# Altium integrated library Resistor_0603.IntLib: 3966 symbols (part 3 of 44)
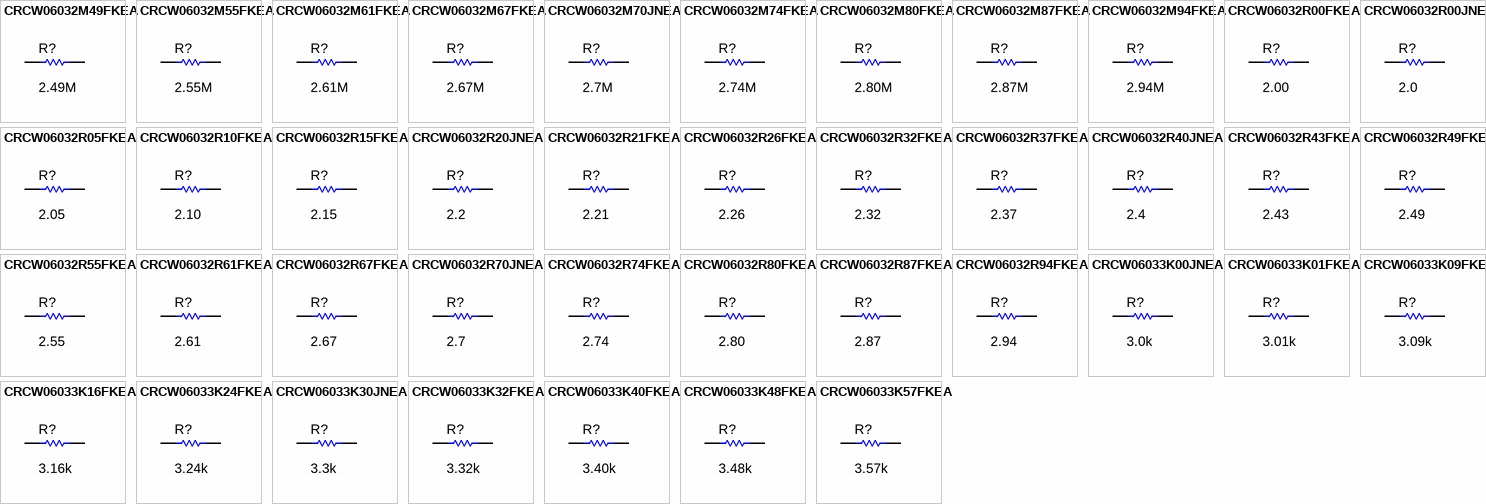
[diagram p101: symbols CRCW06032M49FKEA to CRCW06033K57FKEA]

## CRCW06032R37FKEA
designator R?  ValueDisplayed: 2.37  (hidden comment: CRCW06032R37FKEA)
RES, 2.37, 1%, 0.1 W, 0603; Manufacturer: Vishay-Dale; CompType: Resistor; Value: 2.37; Value_Code: 2R37; Tolerance_%: 1; Power_W: 0.1; Value2: 0.1W; VDC_V: 75; TempCo: 100 ppm/C; SizeArea_mm2: 1.28; SizeX_mm: 1.6; SizeY_mm: 0.8; EIA_Code: E96; U/M: EA; AEC Category: Q200
signal-integrity model Resistor
simulation model Resistor
footprint 0603
footprint 0603M
footprint 0603L
footprint 0603_HV
footprint 0603S
pins: 1, 2

## CRCW06032R40JNEA
designator R?  ValueDisplayed: 2.4  (hidden comment: CRCW06032R40JNEA)
RES, 2.4, 5%, 0.1 W, 0603; Manufacturer: Vishay-Dale; CompType: Resistor; Value: 2.4; Value_Code: 2R40; Tolerance_%: 5; Power_W: 0.1; Value2: 0.1W; VDC_V: 75; TempCo: 200 ppm/C; SizeArea_mm2: 1.28; SizeX_mm: 1.6; SizeY_mm: 0.8; SizeZ_mm: 1; EIA_Code: E24; U/M: EA; AEC Category: Q200
signal-integrity model Resistor
simulation model Resistor
footprint 0603
footprint 0603M
footprint 0603L
footprint 0603_HV
footprint 0603S
pins: 1, 2

## CRCW06032R43FKEA
designator R?  ValueDisplayed: 2.43  (hidden comment: CRCW06032R43FKEA)
RES, 2.43, 1%, 0.1 W, 0603; Manufacturer: Vishay-Dale; CompType: Resistor; Value: 2.43; Value_Code: 2R43; Tolerance_%: 1; Power_W: 0.1; Value2: 0.1W; VDC_V: 75; TempCo: 100 ppm/C; SizeArea_mm2: 1.28; SizeX_mm: 1.6; SizeY_mm: 0.8; EIA_Code: E96; U/M: EA; AEC Category: Q200
signal-integrity model Resistor
simulation model Resistor
footprint 0603
footprint 0603M
footprint 0603L
footprint 0603_HV
footprint 0603S
pins: 1, 2

## CRCW06032R49FKEA
designator R?  ValueDisplayed: 2.49  (hidden comment: CRCW06032R49FKEA)
RES, 2.49, 1%, 0.1 W, 0603; Manufacturer: Vishay-Dale; CompType: Resistor; Value: 2.49; Value_Code: 2R49; Tolerance_%: 1; Power_W: 0.1; Value2: 0.1W; VDC_V: 75; TempCo: 100 ppm/C; SizeArea_mm2: 1.28; SizeX_mm: 1.6; SizeY_mm: 0.8; EIA_Code: E96; U/M: EA; AEC Category: Q200
signal-integrity model Resistor
simulation model Resistor
footprint 0603
footprint 0603M
footprint 0603L
footprint 0603_HV
footprint 0603S
pins: 1, 2

## CRCW06032R55FKEA
designator R?  ValueDisplayed: 2.55  (hidden comment: CRCW06032R55FKEA)
RES, 2.55, 1%, 0.1 W, 0603; Manufacturer: Vishay-Dale; CompType: Resistor; Value: 2.55; Value_Code: 2R55; Tolerance_%: 1; Power_W: 0.1; Value2: 0.1W; VDC_V: 75; TempCo: 100 ppm/C; SizeArea_mm2: 1.28; SizeX_mm: 1.6; SizeY_mm: 0.8; EIA_Code: E96; U/M: EA; AEC Category: Q200
signal-integrity model Resistor
simulation model Resistor
footprint 0603
footprint 0603M
footprint 0603L
footprint 0603_HV
footprint 0603S
pins: 1, 2

## CRCW06032R61FKEA
designator R?  ValueDisplayed: 2.61  (hidden comment: CRCW06032R61FKEA)
RES, 2.61, 1%, 0.1 W, 0603; Manufacturer: Vishay-Dale; CompType: Resistor; Value: 2.61; Value_Code: 2R61; Tolerance_%: 1; Power_W: 0.1; Value2: 0.1W; VDC_V: 75; TempCo: 100 ppm/C; SizeArea_mm2: 1.28; SizeX_mm: 1.6; SizeY_mm: 0.8; EIA_Code: E96; U/M: EA; AEC Category: Q200
signal-integrity model Resistor
simulation model Resistor
footprint 0603
footprint 0603M
footprint 0603L
footprint 0603_HV
footprint 0603S
pins: 1, 2

## CRCW06032R67FKEA
designator R?  ValueDisplayed: 2.67  (hidden comment: CRCW06032R67FKEA)
RES, 2.67, 1%, 0.1 W, 0603; Manufacturer: Vishay-Dale; CompType: Resistor; Value: 2.67; Value_Code: 2R67; Tolerance_%: 1; Power_W: 0.1; Value2: 0.1W; VDC_V: 75; TempCo: 100 ppm/C; SizeArea_mm2: 1.28; SizeX_mm: 1.6; SizeY_mm: 0.8; EIA_Code: E96; U/M: EA; AEC Category: Q200
signal-integrity model Resistor
simulation model Resistor
footprint 0603
footprint 0603M
footprint 0603L
footprint 0603_HV
footprint 0603S
pins: 1, 2

## CRCW06032R70JNEA
designator R?  ValueDisplayed: 2.7  (hidden comment: CRCW06032R70JNEA)
RES, 2.7, 5%, 0.1 W, 0603; Manufacturer: Vishay-Dale; CompType: Resistor; Value: 2.7; Value_Code: 2R70; Tolerance_%: 5; Power_W: 0.1; Value2: 0.1W; VDC_V: 75; TempCo: 200 ppm/C; SizeArea_mm2: 1.28; SizeX_mm: 1.6; SizeY_mm: 0.8; SizeZ_mm: 1; EIA_Code: E24; U/M: EA; AEC Category: Q200
signal-integrity model Resistor
simulation model Resistor
footprint 0603
footprint 0603M
footprint 0603L
footprint 0603_HV
footprint 0603S
pins: 1, 2

## CRCW06032R74FKEA
designator R?  ValueDisplayed: 2.74  (hidden comment: CRCW06032R74FKEA)
RES, 2.74, 1%, 0.1 W, 0603; Manufacturer: Vishay-Dale; CompType: Resistor; Value: 2.74; Value_Code: 2R74; Tolerance_%: 1; Power_W: 0.1; Value2: 0.1W; VDC_V: 75; TempCo: 100 ppm/C; SizeArea_mm2: 1.28; SizeX_mm: 1.6; SizeY_mm: 0.8; EIA_Code: E96; U/M: EA; AEC Category: Q200
signal-integrity model Resistor
simulation model Resistor
footprint 0603
footprint 0603M
footprint 0603L
footprint 0603_HV
footprint 0603S
pins: 1, 2

## CRCW06032R80FKEA
designator R?  ValueDisplayed: 2.80  (hidden comment: CRCW06032R80FKEA)
RES, 2.80, 1%, 0.1 W, 0603; Manufacturer: Vishay-Dale; CompType: Resistor; Value: 2.80; Res_ohm: 2.8; Value_Code: 2R80; Tolerance_%: 1; Power_W: 0.1; Value2: 0.1W; VDC_V: 75; TempCo: 100 ppm/C; SizeArea_mm2: 1.28; SizeX_mm: 1.6; SizeY_mm: 0.8; EIA_Code: E96; U/M: EA; AEC Category: Q200
signal-integrity model Resistor
simulation model Resistor
footprint 0603
footprint 0603M
footprint 0603L
footprint 0603_HV
footprint 0603S
pins: 1, 2

## CRCW06032R87FKEA
designator R?  ValueDisplayed: 2.87  (hidden comment: CRCW06032R87FKEA)
RES, 2.87, 1%, 0.1 W, 0603; Manufacturer: Vishay-Dale; CompType: Resistor; Value: 2.87; Value_Code: 2R87; Tolerance_%: 1; Power_W: 0.1; Value2: 0.1W; VDC_V: 75; TempCo: 100 ppm/C; SizeArea_mm2: 1.28; SizeX_mm: 1.6; SizeY_mm: 0.8; EIA_Code: E96; U/M: EA; AEC Category: Q200
signal-integrity model Resistor
simulation model Resistor
footprint 0603
footprint 0603M
footprint 0603L
footprint 0603_HV
footprint 0603S
pins: 1, 2

## CRCW06032R94FKEA
designator R?  ValueDisplayed: 2.94  (hidden comment: CRCW06032R94FKEA)
RES, 2.94, 1%, 0.1 W, 0603; Manufacturer: Vishay-Dale; CompType: Resistor; Value: 2.94; Value_Code: 2R94; Tolerance_%: 1; Power_W: 0.1; Value2: 0.1W; VDC_V: 75; TempCo: 100 ppm/C; SizeArea_mm2: 1.28; SizeX_mm: 1.6; SizeY_mm: 0.8; EIA_Code: E96; U/M: EA; AEC Category: Q200
signal-integrity model Resistor
simulation model Resistor
footprint 0603
footprint 0603M
footprint 0603L
footprint 0603_HV
footprint 0603S
pins: 1, 2

## CRCW06033K00JNEA
designator R?  ValueDisplayed: 3.0k  (hidden comment: CRCW06033K00JNEA)
RES, 3.0 k, 5%, 0.1 W, 0603; Manufacturer: Vishay-Dale; CompType: Resistor; Value: 3.0k; Res_ohm: 3000; Value_Code: 3k00; Tolerance_%: 5; Power_W: 0.1; Value2: 0.1W; VDC_V: 75; TempCo: 200 ppm/C; SizeArea_mm2: 1.28; SizeX_mm: 1.6; SizeY_mm: 0.8; SizeZ_mm: 1; EIA_Code: E24; U/M: EA; AEC Category: Q200; Green_Lifecycle: Active; Green_REACh: Passed
signal-integrity model Resistor
simulation model Resistor
footprint 0603
footprint 0603M
footprint 0603L
footprint 0603_HV
footprint 0603S
pins: 1, 2

## CRCW06033K01FKEA
designator R?  ValueDisplayed: 3.01k  (hidden comment: CRCW06033K01FKEA)
RES, 3.01 k, 1%, 0.1 W, 0603; Manufacturer: Vishay-Dale; CompType: Resistor; Value: 3.01k; Res_ohm: 3010; Value_Code: 3k01; Tolerance_%: 1; Power_W: 0.1; Value2: 0.1W; VDC_V: 75; TempCo: 100 ppm/C; SizeArea_mm2: 1.28; SizeX_mm: 1.6; SizeY_mm: 0.8; EIA_Code: E96; U/M: EA; AEC Category: Q200; Green_Lifecycle: Active; Green_REACh: Passed
signal-integrity model Resistor
simulation model Resistor
footprint 0603
footprint 0603M
footprint 0603L
footprint 0603_HV
footprint 0603S
pins: 1, 2

## CRCW06033K09FKEA
designator R?  ValueDisplayed: 3.09k  (hidden comment: CRCW06033K09FKEA)
RES, 3.09 k, 1%, 0.1 W, 0603; Manufacturer: Vishay-Dale; CompType: Resistor; Value: 3.09k; Res_ohm: 3090; Value_Code: 3k09; Tolerance_%: 1; Power_W: 0.1; Value2: 0.1W; VDC_V: 75; TempCo: 100 ppm/C; SizeArea_mm2: 1.28; SizeX_mm: 1.6; SizeY_mm: 0.8; EIA_Code: E96; U/M: EA; AEC Category: Q200; Green_Lifecycle: Active; Green_REACh: Passed
signal-integrity model Resistor
simulation model Resistor
footprint 0603
footprint 0603M
footprint 0603L
footprint 0603_HV
footprint 0603S
pins: 1, 2

## CRCW06033K16FKEA
designator R?  ValueDisplayed: 3.16k  (hidden comment: CRCW06033K16FKEA)
RES, 3.16 k, 1%, 0.1 W, 0603; Manufacturer: Vishay-Dale; CompType: Resistor; Value: 3.16k; Res_ohm: 3160; Value_Code: 3k16; Tolerance_%: 1; Power_W: 0.1; Value2: 0.1W; VDC_V: 75; TempCo: 100 ppm/C; SizeArea_mm2: 1.28; SizeX_mm: 1.6; SizeY_mm: 0.8; EIA_Code: E96; U/M: EA; AEC Category: Q200; Green_Lifecycle: Active; Green_REACh: Passed
signal-integrity model Resistor
simulation model Resistor
footprint 0603
footprint 0603M
footprint 0603L
footprint 0603_HV
footprint 0603S
pins: 1, 2

## CRCW06033K24FKEA
designator R?  ValueDisplayed: 3.24k  (hidden comment: CRCW06033K24FKEA)
RES, 3.24 k, 1%, 0.1 W, 0603; Manufacturer: Vishay-Dale; CompType: Resistor; Value: 3.24k; Res_ohm: 3240; Value_Code: 3k24; Tolerance_%: 1; Power_W: 0.1; Value2: 0.1W; VDC_V: 75; TempCo: 100 ppm/C; SizeArea_mm2: 1.28; SizeX_mm: 1.6; SizeY_mm: 0.8; EIA_Code: E96; U/M: EA; AEC Category: Q200; Green_Lifecycle: Active; Green_REACh: Passed
signal-integrity model Resistor
simulation model Resistor
footprint 0603
footprint 0603M
footprint 0603L
footprint 0603_HV
footprint 0603S
pins: 1, 2

## CRCW06033K30JNEA
designator R?  ValueDisplayed: 3.3k  (hidden comment: CRCW06033K30JNEA)
RES, 3.3 k, 5%, 0.1 W, 0603; Manufacturer: Vishay-Dale; CompType: Resistor; Value: 3.3k; Res_ohm: 3300; Value_Code: 3k30; Tolerance_%: 5; Power_W: 0.1; Value2: 0.1W; VDC_V: 75; TempCo: 200 ppm/C; SizeArea_mm2: 1.28; SizeX_mm: 1.6; SizeY_mm: 0.8; SizeZ_mm: 1; EIA_Code: E24; U/M: EA; AEC Category: Q200; Green_Lifecycle: Active; Green_REACh: Passed
signal-integrity model Resistor
simulation model Resistor
footprint 0603
footprint 0603M
footprint 0603L
footprint 0603_HV
footprint 0603S
pins: 1, 2

## CRCW06033K32FKEA
designator R?  ValueDisplayed: 3.32k  (hidden comment: CRCW06033K32FKEA)
RES, 3.32 k, 1%, 0.1 W, 0603; Manufacturer: Vishay-Dale; CompType: Resistor; Value: 3.32k; Res_ohm: 3320; Value_Code: 3k32; Tolerance_%: 1; Power_W: 0.1; Value2: 0.1W; VDC_V: 75; TempCo: 100 ppm/C; SizeArea_mm2: 1.28; SizeX_mm: 1.6; SizeY_mm: 0.8; EIA_Code: E96; U/M: EA; AEC Category: Q200; Green_Lifecycle: Active; Green_REACh: Passed
signal-integrity model Resistor
simulation model Resistor
footprint 0603
footprint 0603M
footprint 0603L
footprint 0603_HV
footprint 0603S
pins: 1, 2

## CRCW06033K40FKEA
designator R?  ValueDisplayed: 3.40k  (hidden comment: CRCW06033K40FKEA)
RES, 3.40 k, 1%, 0.1 W, 0603; Manufacturer: Vishay-Dale; CompType: Resistor; Value: 3.40k; Res_ohm: 3400; Value_Code: 3k40; Tolerance_%: 1; Power_W: 0.1; Value2: 0.1W; VDC_V: 75; TempCo: 100 ppm/C; SizeArea_mm2: 1.28; SizeX_mm: 1.6; SizeY_mm: 0.8; EIA_Code: E96; U/M: EA; AEC Category: Q200; Green_Lifecycle: Active; Green_REACh: Passed
signal-integrity model Resistor
simulation model Resistor
footprint 0603
footprint 0603M
footprint 0603L
footprint 0603_HV
footprint 0603S
pins: 1, 2

## CRCW06033K48FKEA
designator R?  ValueDisplayed: 3.48k  (hidden comment: CRCW06033K48FKEA)
RES, 3.48 k, 1%, 0.1 W, 0603; Manufacturer: Vishay-Dale; CompType: Resistor; Value: 3.48k; Res_ohm: 3480; Value_Code: 3k48; Tolerance_%: 1; Power_W: 0.1; Value2: 0.1W; VDC_V: 75; TempCo: 100 ppm/C; SizeArea_mm2: 1.28; SizeX_mm: 1.6; SizeY_mm: 0.8; EIA_Code: E96; U/M: EA; AEC Category: Q200; Green_Lifecycle: Active; Green_REACh: Passed
signal-integrity model Resistor
simulation model Resistor
footprint 0603
footprint 0603M
footprint 0603L
footprint 0603_HV
footprint 0603S
pins: 1, 2

## CRCW06033K57FKEA
designator R?  ValueDisplayed: 3.57k  (hidden comment: CRCW06033K57FKEA)
RES, 3.57 k, 1%, 0.1 W, 0603; Manufacturer: Vishay-Dale; CompType: Resistor; Value: 3.57k; Res_ohm: 3570; Value_Code: 3k57; Tolerance_%: 1; Power_W: 0.1; Value2: 0.1W; VDC_V: 75; TempCo: 100 ppm/C; SizeArea_mm2: 1.28; SizeX_mm: 1.6; SizeY_mm: 0.8; EIA_Code: E96; U/M: EA; AEC Category: Q200; Green_Lifecycle: Active; Green_REACh: Passed
signal-integrity model Resistor
simulation model Resistor
footprint 0603
footprint 0603M
footprint 0603L
footprint 0603_HV
footprint 0603S
pins: 1, 2

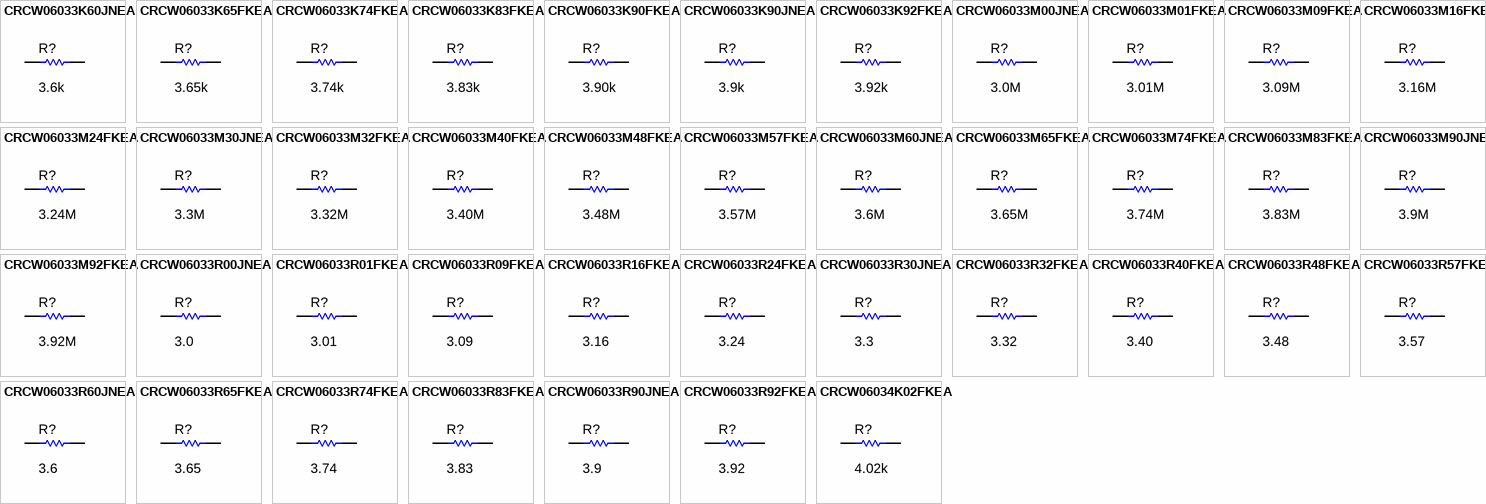
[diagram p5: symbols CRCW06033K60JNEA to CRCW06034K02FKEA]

## CRCW06033K60JNEA
designator R?  ValueDisplayed: 3.6k  (hidden comment: CRCW06033K60JNEA)
RES, 3.6 k, 5%, 0.1 W, 0603; Manufacturer: Vishay-Dale; CompType: Resistor; Value: 3.6k; Res_ohm: 3600; Value_Code: 3k60; Tolerance_%: 5; Power_W: 0.1; Value2: 0.1W; VDC_V: 75; TempCo: 200 ppm/C; SizeArea_mm2: 1.28; SizeX_mm: 1.6; SizeY_mm: 0.8; SizeZ_mm: 1; EIA_Code: E24; U/M: EA; AEC Category: Q200
signal-integrity model Resistor
simulation model Resistor
footprint 0603
footprint 0603M
footprint 0603L
footprint 0603_HV
footprint 0603S
pins: 1, 2

## CRCW06033K65FKEA
designator R?  ValueDisplayed: 3.65k  (hidden comment: CRCW06033K65FKEA)
RES, 3.65 k, 1%, 0.1 W, 0603; Manufacturer: Vishay-Dale; CompType: Resistor; Value: 3.65k; Res_ohm: 3650; Value_Code: 3k65; Tolerance_%: 1; Power_W: 0.1; Value2: 0.1W; VDC_V: 75; TempCo: 100 ppm/C; SizeArea_mm2: 1.28; SizeX_mm: 1.6; SizeY_mm: 0.8; EIA_Code: E96; U/M: EA; AEC Category: Q200; Green_Lifecycle: Active; Green_REACh: Passed
signal-integrity model Resistor
simulation model Resistor
footprint 0603
footprint 0603M
footprint 0603L
footprint 0603_HV
footprint 0603S
pins: 1, 2

## CRCW06033K74FKEA
designator R?  ValueDisplayed: 3.74k  (hidden comment: CRCW06033K74FKEA)
RES, 3.74 k, 1%, 0.1 W, 0603; Manufacturer: Vishay-Dale; CompType: Resistor; Value: 3.74k; Res_ohm: 3740; Value_Code: 3k74; Tolerance_%: 1; Power_W: 0.1; Value2: 0.1W; VDC_V: 75; TempCo: 100 ppm/C; SizeArea_mm2: 1.28; SizeX_mm: 1.6; SizeY_mm: 0.8; EIA_Code: E96; U/M: EA; AEC Category: Q200; Green_Lifecycle: Active; Green_REACh: Passed
signal-integrity model Resistor
simulation model Resistor
footprint 0603
footprint 0603M
footprint 0603L
footprint 0603_HV
footprint 0603S
pins: 1, 2

## CRCW06033K83FKEA
designator R?  ValueDisplayed: 3.83k  (hidden comment: CRCW06033K83FKEA)
RES, 3.83 k, 1%, 0.1 W, 0603; Manufacturer: Vishay-Dale; CompType: Resistor; Value: 3.83k; Res_ohm: 3830; Value_Code: 3k83; Tolerance_%: 1; Power_W: 0.1; Value2: 0.1W; VDC_V: 75; TempCo: 100 ppm/C; SizeArea_mm2: 1.28; SizeX_mm: 1.6; SizeY_mm: 0.8; EIA_Code: E96; U/M: EA; AEC Category: Q200; Green_Lifecycle: Active; Green_REACh: Passed
signal-integrity model Resistor
simulation model Resistor
footprint 0603
footprint 0603M
footprint 0603L
footprint 0603_HV
footprint 0603S
pins: 1, 2

## CRCW06033K90FKEA
designator R?  ValueDisplayed: 3.90k  (hidden comment: CRCW06033K90FKEA)
RES, 3.90 k, 1%, 0.1 W, 0603; Manufacturer: Vishay-Dale; CompType: Resistor; Value: 3.90k; Res_ohm: 3900; Value_Code: 3k90; Tolerance_%: 1; Power_W: 0.1; Value2: 0.1W; TempCo: 100 ppm/C; SizeArea_mm2: 1.28; SizeX_mm: 1.6; SizeY_mm: 0.8; U/M: EA; AEC Category: Q200
signal-integrity model Resistor
simulation model Resistor
footprint 0603
footprint 0603M
footprint 0603L
footprint 0603_HV
footprint 0603S
pins: 1, 2

## CRCW06033K90JNEA
designator R?  ValueDisplayed: 3.9k  (hidden comment: CRCW06033K90JNEA)
RES, 3.9 k, 5%, 0.1 W, 0603; Manufacturer: Vishay-Dale; CompType: Resistor; Value: 3.9k; Res_ohm: 3900; Value_Code: 3k90; Tolerance_%: 5; Power_W: 0.1; Value2: 0.1W; VDC_V: 75; TempCo: 200 ppm/C; SizeArea_mm2: 1.28; SizeX_mm: 1.6; SizeY_mm: 0.8; SizeZ_mm: 1; EIA_Code: E24; U/M: EA; AEC Category: Q200; Green_Lifecycle: Active; Green_REACh: Passed
signal-integrity model Resistor
simulation model Resistor
footprint 0603
footprint 0603M
footprint 0603L
footprint 0603_HV
footprint 0603S
pins: 1, 2

## CRCW06033K92FKEA
designator R?  ValueDisplayed: 3.92k  (hidden comment: CRCW06033K92FKEA)
RES, 3.92 k, 1%, 0.1 W, 0603; Manufacturer: Vishay-Dale; CompType: Resistor; Value: 3.92k; Res_ohm: 3920; Value_Code: 3k92; Tolerance_%: 1; Power_W: 0.1; Value2: 0.1W; VDC_V: 75; TempCo: 100 ppm/C; SizeArea_mm2: 1.28; SizeX_mm: 1.6; SizeY_mm: 0.8; EIA_Code: E96; U/M: EA; AEC Category: Q200; Green_Lifecycle: Active; Green_REACh: Passed
signal-integrity model Resistor
simulation model Resistor
footprint 0603
footprint 0603M
footprint 0603L
footprint 0603_HV
footprint 0603S
pins: 1, 2

## CRCW06033M00JNEA
designator R?  ValueDisplayed: 3.0M  (hidden comment: CRCW06033M00JNEA)
RES, 3.0 M, 5%, 0.1 W, 0603; Manufacturer: Vishay-Dale; CompType: Resistor; Value: 3.0Meg; Res_ohm: 3000000; Value_Code: 3M00; Tolerance_%: 5; Power_W: 0.1; Value2: 0.1W; VDC_V: 75; TempCo: 200 ppm/C; SizeArea_mm2: 1.28; SizeX_mm: 1.6; SizeY_mm: 0.8; SizeZ_mm: 1; EIA_Code: E24; U/M: EA; AEC Category: Q200; Green_Lifecycle: Active; Green_REACh: Passed
signal-integrity model Resistor
simulation model Resistor
footprint 0603
footprint 0603M
footprint 0603L
footprint 0603_HV
footprint 0603S
pins: 1, 2

## CRCW06033M01FKEA
designator R?  ValueDisplayed: 3.01M  (hidden comment: CRCW06033M01FKEA)
RES, 3.01 M, 1%, 0.1 W, 0603; Manufacturer: Vishay-Dale; CompType: Resistor; Value: 3.01Meg; Res_ohm: 3010000; Value_Code: 3M01; Tolerance_%: 1; Power_W: 0.1; Value2: 0.1W; VDC_V: 75; TempCo: 100 ppm/C; SizeArea_mm2: 1.28; SizeX_mm: 1.6; SizeY_mm: 0.8; EIA_Code: E96; U/M: EA; AEC Category: Q200; Green_Lifecycle: Active; Green_REACh: Passed
signal-integrity model Resistor
simulation model Resistor
footprint 0603
footprint 0603M
footprint 0603L
footprint 0603_HV
footprint 0603S
pins: 1, 2

## CRCW06033M09FKEA
designator R?  ValueDisplayed: 3.09M  (hidden comment: CRCW06033M09FKEA)
RES, 3.09 M, 1%, 0.1 W, 0603; Manufacturer: Vishay-Dale; CompType: Resistor; Value: 3.09Meg; Res_ohm: 3090000; Value_Code: 3M09; Tolerance_%: 1; Power_W: 0.1; Value2: 0.1W; VDC_V: 75; TempCo: 100 ppm/C; SizeArea_mm2: 1.28; SizeX_mm: 1.6; SizeY_mm: 0.8; EIA_Code: E96; U/M: EA; AEC Category: Q200
signal-integrity model Resistor
simulation model Resistor
footprint 0603
footprint 0603M
footprint 0603L
footprint 0603_HV
footprint 0603S
pins: 1, 2

## CRCW06033M16FKEA
designator R?  ValueDisplayed: 3.16M  (hidden comment: CRCW06033M16FKEA)
RES, 3.16 M, 1%, 0.1 W, 0603; Manufacturer: Vishay-Dale; CompType: Resistor; Value: 3.16Meg; Res_ohm: 3160000; Value_Code: 3M16; Tolerance_%: 1; Power_W: 0.1; Value2: 0.1W; VDC_V: 75; TempCo: 100 ppm/C; SizeArea_mm2: 1.28; SizeX_mm: 1.6; SizeY_mm: 0.8; EIA_Code: E96; U/M: EA; AEC Category: Q200
signal-integrity model Resistor
simulation model Resistor
footprint 0603
footprint 0603M
footprint 0603L
footprint 0603_HV
footprint 0603S
pins: 1, 2

## CRCW06033M24FKEA
designator R?  ValueDisplayed: 3.24M  (hidden comment: CRCW06033M24FKEA)
RES, 3.24 M, 1%, 0.1 W, 0603; Manufacturer: Vishay-Dale; CompType: Resistor; Value: 3.24Meg; Res_ohm: 3240000; Value_Code: 3M24; Tolerance_%: 1; Power_W: 0.1; Value2: 0.1W; VDC_V: 75; TempCo: 100 ppm/C; SizeArea_mm2: 1.28; SizeX_mm: 1.6; SizeY_mm: 0.8; EIA_Code: E96; U/M: EA; AEC Category: Q200
signal-integrity model Resistor
simulation model Resistor
footprint 0603
footprint 0603M
footprint 0603L
footprint 0603_HV
footprint 0603S
pins: 1, 2

## CRCW06033M30JNEA
designator R?  ValueDisplayed: 3.3M  (hidden comment: CRCW06033M30JNEA)
RES, 3.3 M, 5%, 0.1 W, 0603; Manufacturer: Vishay-Dale; CompType: Resistor; Value: 3.3Meg; Res_ohm: 3300000; Value_Code: 3M30; Tolerance_%: 5; Power_W: 0.1; Value2: 0.1W; VDC_V: 75; TempCo: 200 ppm/C; SizeArea_mm2: 1.28; SizeX_mm: 1.6; SizeY_mm: 0.8; SizeZ_mm: 1; EIA_Code: E24; U/M: EA; AEC Category: Q200; Green_Lifecycle: Active; Green_REACh: Passed
signal-integrity model Resistor
simulation model Resistor
footprint 0603
footprint 0603M
footprint 0603L
footprint 0603_HV
footprint 0603S
pins: 1, 2

## CRCW06033M32FKEA
designator R?  ValueDisplayed: 3.32M  (hidden comment: CRCW06033M32FKEA)
RES, 3.32 M, 1%, 0.1 W, 0603; Manufacturer: Vishay-Dale; CompType: Resistor; Value: 3.32Meg; Res_ohm: 3320000; Value_Code: 3M32; Tolerance_%: 1; Power_W: 0.1; Value2: 0.1W; VDC_V: 75; TempCo: 100 ppm/C; SizeArea_mm2: 1.28; SizeX_mm: 1.6; SizeY_mm: 0.8; EIA_Code: E96; U/M: EA; AEC Category: Q200
signal-integrity model Resistor
simulation model Resistor
footprint 0603
footprint 0603M
footprint 0603L
footprint 0603_HV
footprint 0603S
pins: 1, 2

## CRCW06033M40FKEA
designator R?  ValueDisplayed: 3.40M  (hidden comment: CRCW06033M40FKEA)
RES, 3.40 M, 1%, 0.1 W, 0603; Manufacturer: Vishay-Dale; CompType: Resistor; Value: 3.40Meg; Res_ohm: 3400000; Value_Code: 3M40; Tolerance_%: 1; Power_W: 0.1; Value2: 0.1W; VDC_V: 75; TempCo: 100 ppm/C; SizeArea_mm2: 1.28; SizeX_mm: 1.6; SizeY_mm: 0.8; EIA_Code: E96; U/M: EA; AEC Category: Q200; Green_Lifecycle: Active; Green_REACh: Passed
signal-integrity model Resistor
simulation model Resistor
footprint 0603
footprint 0603M
footprint 0603L
footprint 0603_HV
footprint 0603S
pins: 1, 2

## CRCW06033M48FKEA
designator R?  ValueDisplayed: 3.48M  (hidden comment: CRCW06033M48FKEA)
RES, 3.48 M, 1%, 0.1 W, 0603; Manufacturer: Vishay-Dale; CompType: Resistor; Value: 3.48Meg; Res_ohm: 3480000; Value_Code: 3M48; Tolerance_%: 1; Power_W: 0.1; Value2: 0.1W; VDC_V: 75; TempCo: 100 ppm/C; SizeArea_mm2: 1.28; SizeX_mm: 1.6; SizeY_mm: 0.8; EIA_Code: E96; U/M: EA; AEC Category: Q200
signal-integrity model Resistor
simulation model Resistor
footprint 0603
footprint 0603M
footprint 0603L
footprint 0603_HV
footprint 0603S
pins: 1, 2

## CRCW06033M57FKEA
designator R?  ValueDisplayed: 3.57M  (hidden comment: CRCW06033M57FKEA)
RES, 3.57 M, 1%, 0.1 W, 0603; Manufacturer: Vishay-Dale; CompType: Resistor; Value: 3.57Meg; Res_ohm: 3570000; Value_Code: 3M57; Tolerance_%: 1; Power_W: 0.1; Value2: 0.1W; VDC_V: 75; TempCo: 100 ppm/C; SizeArea_mm2: 1.28; SizeX_mm: 1.6; SizeY_mm: 0.8; EIA_Code: E96; U/M: EA; AEC Category: Q200
signal-integrity model Resistor
simulation model Resistor
footprint 0603
footprint 0603M
footprint 0603L
footprint 0603_HV
footprint 0603S
pins: 1, 2

## CRCW06033M60JNEA
designator R?  ValueDisplayed: 3.6M  (hidden comment: CRCW06033M60JNEA)
RES, 3.6 M, 5%, 0.1 W, 0603; Manufacturer: Vishay-Dale; CompType: Resistor; Value: 3.6Meg; Res_ohm: 3600000; Value_Code: 3M60; Tolerance_%: 5; Power_W: 0.1; Value2: 0.1W; VDC_V: 75; TempCo: 200 ppm/C; SizeArea_mm2: 1.28; SizeX_mm: 1.6; SizeY_mm: 0.8; SizeZ_mm: 1; EIA_Code: E24; U/M: EA; AEC Category: Q200
signal-integrity model Resistor
simulation model Resistor
footprint 0603
footprint 0603M
footprint 0603L
footprint 0603_HV
footprint 0603S
pins: 1, 2

## CRCW06033M65FKEA
designator R?  ValueDisplayed: 3.65M  (hidden comment: CRCW06033M65FKEA)
RES, 3.65 M, 1%, 0.1 W, 0603; Manufacturer: Vishay-Dale; CompType: Resistor; Value: 3.65Meg; Res_ohm: 3650000; Value_Code: 3M65; Tolerance_%: 1; Power_W: 0.1; Value2: 0.1W; VDC_V: 75; TempCo: 100 ppm/C; SizeArea_mm2: 1.28; SizeX_mm: 1.6; SizeY_mm: 0.8; EIA_Code: E96; U/M: EA; AEC Category: Q200
signal-integrity model Resistor
simulation model Resistor
footprint 0603
footprint 0603M
footprint 0603L
footprint 0603_HV
footprint 0603S
pins: 1, 2

## CRCW06033M74FKEA
designator R?  ValueDisplayed: 3.74M  (hidden comment: CRCW06033M74FKEA)
RES, 3.74 M, 1%, 0.1 W, 0603; Manufacturer: Vishay-Dale; CompType: Resistor; Value: 3.74Meg; Res_ohm: 3740000; Value_Code: 3M74; Tolerance_%: 1; Power_W: 0.1; Value2: 0.1W; VDC_V: 75; TempCo: 100 ppm/C; SizeArea_mm2: 1.28; SizeX_mm: 1.6; SizeY_mm: 0.8; EIA_Code: E96; U/M: EA; AEC Category: Q200
signal-integrity model Resistor
simulation model Resistor
footprint 0603
footprint 0603M
footprint 0603L
footprint 0603_HV
footprint 0603S
pins: 1, 2

## CRCW06033M83FKEA
designator R?  ValueDisplayed: 3.83M  (hidden comment: CRCW06033M83FKEA)
RES, 3.83 M, 1%, 0.1 W, 0603; Manufacturer: Vishay-Dale; CompType: Resistor; Value: 3.83Meg; Res_ohm: 3830000; Value_Code: 3M83; Tolerance_%: 1; Power_W: 0.1; Value2: 0.1W; VDC_V: 75; TempCo: 100 ppm/C; SizeArea_mm2: 1.28; SizeX_mm: 1.6; SizeY_mm: 0.8; EIA_Code: E96; U/M: EA; AEC Category: Q200
signal-integrity model Resistor
simulation model Resistor
footprint 0603
footprint 0603M
footprint 0603L
footprint 0603_HV
footprint 0603S
pins: 1, 2

## CRCW06033M90JNEA
designator R?  ValueDisplayed: 3.9M  (hidden comment: CRCW06033M90JNEA)
RES, 3.9 M, 5%, 0.1 W, 0603; Manufacturer: Vishay-Dale; CompType: Resistor; Value: 3.9Meg; Res_ohm: 3900000; Value_Code: 3M90; Tolerance_%: 5; Power_W: 0.1; Value2: 0.1W; VDC_V: 75; TempCo: 200 ppm/C; SizeArea_mm2: 1.28; SizeX_mm: 1.6; SizeY_mm: 0.8; SizeZ_mm: 1; EIA_Code: E24; U/M: EA; AEC Category: Q200
signal-integrity model Resistor
simulation model Resistor
footprint 0603
footprint 0603M
footprint 0603L
footprint 0603_HV
footprint 0603S
pins: 1, 2

## CRCW06033M92FKEA
designator R?  ValueDisplayed: 3.92M  (hidden comment: CRCW06033M92FKEA)
RES, 3.92 M, 1%, 0.1 W, 0603; Manufacturer: Vishay-Dale; CompType: Resistor; Value: 3.92Meg; Res_ohm: 3920000; Value_Code: 3M92; Tolerance_%: 1; Power_W: 0.1; Value2: 0.1W; VDC_V: 75; TempCo: 100 ppm/C; SizeArea_mm2: 1.28; SizeX_mm: 1.6; SizeY_mm: 0.8; EIA_Code: E96; U/M: EA; AEC Category: Q200
signal-integrity model Resistor
simulation model Resistor
footprint 0603
footprint 0603M
footprint 0603L
footprint 0603_HV
footprint 0603S
pins: 1, 2

## CRCW06033R00JNEA
designator R?  ValueDisplayed: 3.0  (hidden comment: CRCW06033R00JNEA)
RES, 3.0, 5%, 0.1 W, 0603; Manufacturer: Vishay-Dale; CompType: Resistor; Value: 3.0; Res_ohm: 3; Value_Code: 3R00; Tolerance_%: 5; Power_W: 0.1; Value2: 0.1W; VDC_V: 75; TempCo: 200 ppm/C; SizeArea_mm2: 1.28; SizeX_mm: 1.6; SizeY_mm: 0.8; SizeZ_mm: 1; EIA_Code: E24; U/M: EA; AEC Category: Q200; Green_Lifecycle: Active; Green_REACh: Passed
signal-integrity model Resistor
simulation model Resistor
footprint 0603
footprint 0603M
footprint 0603L
footprint 0603_HV
footprint 0603S
pins: 1, 2

## CRCW06033R01FKEA
designator R?  ValueDisplayed: 3.01  (hidden comment: CRCW06033R01FKEA)
RES, 3.01, 1%, 0.1 W, 0603; Manufacturer: Vishay-Dale; CompType: Resistor; Value: 3.01; Value_Code: 3R01; Tolerance_%: 1; Power_W: 0.1; Value2: 0.1W; VDC_V: 75; TempCo: 100 ppm/C; SizeArea_mm2: 1.28; SizeX_mm: 1.6; SizeY_mm: 0.8; EIA_Code: E96; U/M: EA; AEC Category: Q200; Green_Lifecycle: Active; Green_REACh: Passed
signal-integrity model Resistor
simulation model Resistor
footprint 0603
footprint 0603M
footprint 0603L
footprint 0603_HV
footprint 0603S
pins: 1, 2

## CRCW06033R09FKEA
designator R?  ValueDisplayed: 3.09  (hidden comment: CRCW06033R09FKEA)
RES, 3.09, 1%, 0.1 W, 0603; Manufacturer: Vishay-Dale; CompType: Resistor; Value: 3.09; Value_Code: 3R09; Tolerance_%: 1; Power_W: 0.1; Value2: 0.1W; VDC_V: 75; TempCo: 100 ppm/C; SizeArea_mm2: 1.28; SizeX_mm: 1.6; SizeY_mm: 0.8; EIA_Code: E96; U/M: EA; AEC Category: Q200
signal-integrity model Resistor
simulation model Resistor
footprint 0603
footprint 0603M
footprint 0603L
footprint 0603_HV
footprint 0603S
pins: 1, 2

## CRCW06033R16FKEA
designator R?  ValueDisplayed: 3.16  (hidden comment: CRCW06033R16FKEA)
RES, 3.16, 1%, 0.1 W, 0603; Manufacturer: Vishay-Dale; CompType: Resistor; Value: 3.16; Value_Code: 3R16; Tolerance_%: 1; Power_W: 0.1; Value2: 0.1W; VDC_V: 75; TempCo: 100 ppm/C; SizeArea_mm2: 1.28; SizeX_mm: 1.6; SizeY_mm: 0.8; EIA_Code: E96; U/M: EA; AEC Category: Q200
signal-integrity model Resistor
simulation model Resistor
footprint 0603
footprint 0603M
footprint 0603L
footprint 0603_HV
footprint 0603S
pins: 1, 2

## CRCW06033R24FKEA
designator R?  ValueDisplayed: 3.24  (hidden comment: CRCW06033R24FKEA)
RES, 3.24, 1%, 0.1 W, 0603; Manufacturer: Vishay-Dale; CompType: Resistor; Value: 3.24; Value_Code: 3R24; Tolerance_%: 1; Power_W: 0.1; Value2: 0.1W; VDC_V: 75; TempCo: 100 ppm/C; SizeArea_mm2: 1.28; SizeX_mm: 1.6; SizeY_mm: 0.8; EIA_Code: E96; U/M: EA; AEC Category: Q200
signal-integrity model Resistor
simulation model Resistor
footprint 0603
footprint 0603M
footprint 0603L
footprint 0603_HV
footprint 0603S
pins: 1, 2

## CRCW06033R30JNEA
designator R?  ValueDisplayed: 3.3  (hidden comment: CRCW06033R30JNEA)
RES, 3.3, 5%, 0.1 W, 0603; Manufacturer: Vishay-Dale; CompType: Resistor; Value: 3.3; Value_Code: 3R30; Tolerance_%: 5; Power_W: 0.1; Value2: 0.1W; VDC_V: 75; TempCo: 200 ppm/C; SizeArea_mm2: 1.28; SizeX_mm: 1.6; SizeY_mm: 0.8; SizeZ_mm: 1; EIA_Code: E24; U/M: EA; AEC Category: Q200; Green_Lifecycle: Active; Green_REACh: Passed
signal-integrity model Resistor
simulation model Resistor
footprint 0603
footprint 0603M
footprint 0603L
footprint 0603_HV
footprint 0603S
pins: 1, 2

## CRCW06033R32FKEA
designator R?  ValueDisplayed: 3.32  (hidden comment: CRCW06033R32FKEA)
RES, 3.32, 1%, 0.1 W, 0603; Manufacturer: Vishay-Dale; CompType: Resistor; Value: 3.32; Value_Code: 3R32; Tolerance_%: 1; Power_W: 0.1; Value2: 0.1W; VDC_V: 75; TempCo: 100 ppm/C; SizeArea_mm2: 1.28; SizeX_mm: 1.6; SizeY_mm: 0.8; EIA_Code: E96; U/M: EA; AEC Category: Q200
signal-integrity model Resistor
simulation model Resistor
footprint 0603
footprint 0603M
footprint 0603L
footprint 0603_HV
footprint 0603S
pins: 1, 2

## CRCW06033R40FKEA
designator R?  ValueDisplayed: 3.40  (hidden comment: CRCW06033R40FKEA)
RES, 3.40, 1%, 0.1 W, 0603; Manufacturer: Vishay-Dale; CompType: Resistor; Value: 3.40; Res_ohm: 3.4; Value_Code: 3R40; Tolerance_%: 1; Power_W: 0.1; Value2: 0.1W; VDC_V: 75; TempCo: 100 ppm/C; SizeArea_mm2: 1.28; SizeX_mm: 1.6; SizeY_mm: 0.8; EIA_Code: E96; U/M: EA; AEC Category: Q200; Green_Lifecycle: Active; Green_REACh: Passed
signal-integrity model Resistor
simulation model Resistor
footprint 0603
footprint 0603M
footprint 0603L
footprint 0603_HV
footprint 0603S
pins: 1, 2

## CRCW06033R48FKEA
designator R?  ValueDisplayed: 3.48  (hidden comment: CRCW06033R48FKEA)
RES, 3.48, 1%, 0.1 W, 0603; Manufacturer: Vishay-Dale; CompType: Resistor; Value: 3.48; Value_Code: 3R48; Tolerance_%: 1; Power_W: 0.1; Value2: 0.1W; VDC_V: 75; TempCo: 100 ppm/C; SizeArea_mm2: 1.28; SizeX_mm: 1.6; SizeY_mm: 0.8; EIA_Code: E96; U/M: EA; AEC Category: Q200
signal-integrity model Resistor
simulation model Resistor
footprint 0603
footprint 0603M
footprint 0603L
footprint 0603_HV
footprint 0603S
pins: 1, 2

## CRCW06033R57FKEA
designator R?  ValueDisplayed: 3.57  (hidden comment: CRCW06033R57FKEA)
RES, 3.57, 1%, 0.1 W, 0603; Manufacturer: Vishay-Dale; CompType: Resistor; Value: 3.57; Value_Code: 3R57; Tolerance_%: 1; Power_W: 0.1; Value2: 0.1W; VDC_V: 75; TempCo: 100 ppm/C; SizeArea_mm2: 1.28; SizeX_mm: 1.6; SizeY_mm: 0.8; EIA_Code: E96; U/M: EA; AEC Category: Q200
signal-integrity model Resistor
simulation model Resistor
footprint 0603
footprint 0603M
footprint 0603L
footprint 0603_HV
footprint 0603S
pins: 1, 2

## CRCW06033R60JNEA
designator R?  ValueDisplayed: 3.6  (hidden comment: CRCW06033R60JNEA)
RES, 3.6, 5%, 0.1 W, 0603; Manufacturer: Vishay-Dale; CompType: Resistor; Value: 3.6; Value_Code: 3R60; Tolerance_%: 5; Power_W: 0.1; Value2: 0.1W; VDC_V: 75; TempCo: 200 ppm/C; SizeArea_mm2: 1.28; SizeX_mm: 1.6; SizeY_mm: 0.8; SizeZ_mm: 1; EIA_Code: E24; U/M: EA; AEC Category: Q200
signal-integrity model Resistor
simulation model Resistor
footprint 0603
footprint 0603M
footprint 0603L
footprint 0603_HV
footprint 0603S
pins: 1, 2

## CRCW06033R65FKEA
designator R?  ValueDisplayed: 3.65  (hidden comment: CRCW06033R65FKEA)
RES, 3.65, 1%, 0.1 W, 0603; Manufacturer: Vishay-Dale; CompType: Resistor; Value: 3.65; Value_Code: 3R65; Tolerance_%: 1; Power_W: 0.1; Value2: 0.1W; VDC_V: 75; TempCo: 100 ppm/C; SizeArea_mm2: 1.28; SizeX_mm: 1.6; SizeY_mm: 0.8; EIA_Code: E96; U/M: EA; AEC Category: Q200
signal-integrity model Resistor
simulation model Resistor
footprint 0603
footprint 0603M
footprint 0603L
footprint 0603_HV
footprint 0603S
pins: 1, 2

## CRCW06033R74FKEA
designator R?  ValueDisplayed: 3.74  (hidden comment: CRCW06033R74FKEA)
RES, 3.74, 1%, 0.1 W, 0603; Manufacturer: Vishay-Dale; CompType: Resistor; Value: 3.74; Value_Code: 3R74; Tolerance_%: 1; Power_W: 0.1; Value2: 0.1W; VDC_V: 75; TempCo: 100 ppm/C; SizeArea_mm2: 1.28; SizeX_mm: 1.6; SizeY_mm: 0.8; EIA_Code: E96; U/M: EA; AEC Category: Q200
signal-integrity model Resistor
simulation model Resistor
footprint 0603
footprint 0603M
footprint 0603L
footprint 0603_HV
footprint 0603S
pins: 1, 2

## CRCW06033R83FKEA
designator R?  ValueDisplayed: 3.83  (hidden comment: CRCW06033R83FKEA)
RES, 3.83, 1%, 0.1 W, 0603; Manufacturer: Vishay-Dale; CompType: Resistor; Value: 3.83; Value_Code: 3R83; Tolerance_%: 1; Power_W: 0.1; Value2: 0.1W; VDC_V: 75; TempCo: 100 ppm/C; SizeArea_mm2: 1.28; SizeX_mm: 1.6; SizeY_mm: 0.8; EIA_Code: E96; U/M: EA; AEC Category: Q200
signal-integrity model Resistor
simulation model Resistor
footprint 0603
footprint 0603M
footprint 0603L
footprint 0603_HV
footprint 0603S
pins: 1, 2

## CRCW06033R90JNEA
designator R?  ValueDisplayed: 3.9  (hidden comment: CRCW06033R90JNEA)
RES, 3.9, 5%, 0.1 W, 0603; Manufacturer: Vishay-Dale; CompType: Resistor; Value: 3.9; Value_Code: 3R90; Tolerance_%: 5; Power_W: 0.1; Value2: 0.1W; VDC_V: 75; TempCo: 200 ppm/C; SizeArea_mm2: 1.28; SizeX_mm: 1.6; SizeY_mm: 0.8; SizeZ_mm: 1; EIA_Code: E24; U/M: EA; AEC Category: Q200
signal-integrity model Resistor
simulation model Resistor
footprint 0603
footprint 0603M
footprint 0603L
footprint 0603_HV
footprint 0603S
pins: 1, 2

## CRCW06033R92FKEA
designator R?  ValueDisplayed: 3.92  (hidden comment: CRCW06033R92FKEA)
RES, 3.92, 1%, 0.1 W, 0603; Manufacturer: Vishay-Dale; CompType: Resistor; Value: 3.92; Value_Code: 3R92; Tolerance_%: 1; Power_W: 0.1; Value2: 0.1W; VDC_V: 75; TempCo: 100 ppm/C; SizeArea_mm2: 1.28; SizeX_mm: 1.6; SizeY_mm: 0.8; EIA_Code: E96; U/M: EA; AEC Category: Q200
signal-integrity model Resistor
simulation model Resistor
footprint 0603
footprint 0603M
footprint 0603L
footprint 0603_HV
footprint 0603S
pins: 1, 2

## CRCW06034K02FKEA
designator R?  ValueDisplayed: 4.02k  (hidden comment: CRCW06034K02FKEA)
RES, 4.02 k, 1%, 0.1 W, 0603; Manufacturer: Vishay-Dale; CompType: Resistor; Value: 4.02k; Res_ohm: 4020; Value_Code: 4k02; Tolerance_%: 1; Power_W: 0.1; Value2: 0.1W; VDC_V: 75; TempCo: 100 ppm/C; SizeArea_mm2: 1.28; SizeX_mm: 1.6; SizeY_mm: 0.8; EIA_Code: E96; U/M: EA; AEC Category: Q200; Green_Lifecycle: Active; Green_REACh: Passed
signal-integrity model Resistor
simulation model Resistor
footprint 0603
footprint 0603M
footprint 0603L
footprint 0603_HV
footprint 0603S
pins: 1, 2

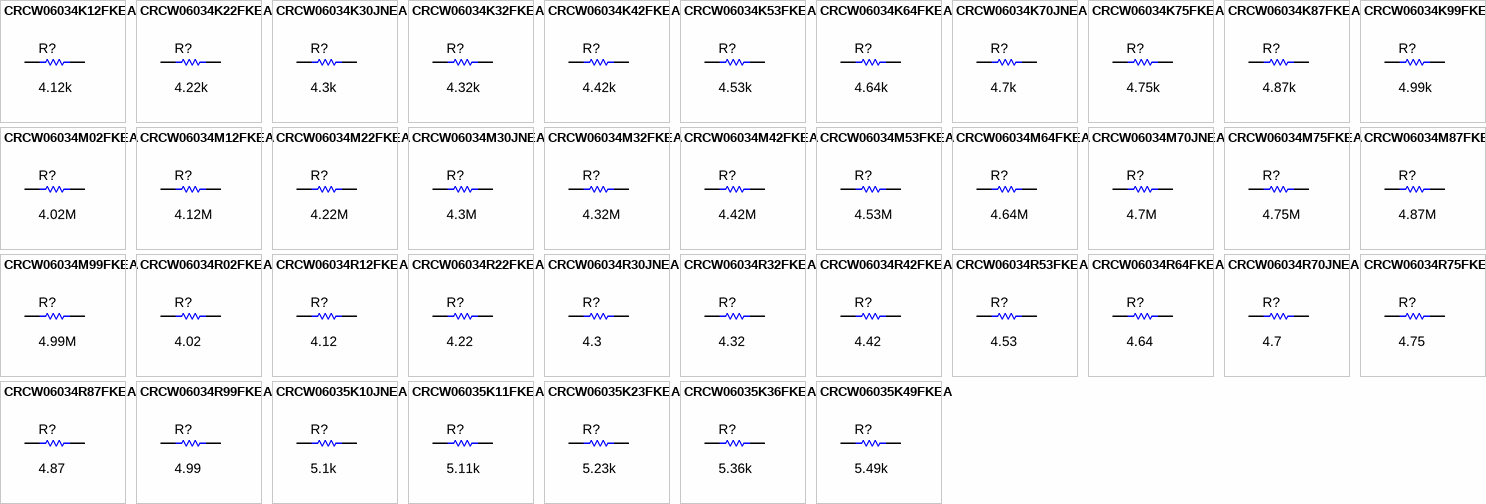
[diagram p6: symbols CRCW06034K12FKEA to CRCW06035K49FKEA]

## CRCW06034K12FKEA
designator R?  ValueDisplayed: 4.12k  (hidden comment: CRCW06034K12FKEA)
RES, 4.12 k, 1%, 0.1 W, 0603; Manufacturer: Vishay-Dale; CompType: Resistor; Value: 4.12k; Res_ohm: 4120; Value_Code: 4k12; Tolerance_%: 1; Power_W: 0.1; Value2: 0.1W; VDC_V: 75; TempCo: 100 ppm/C; SizeArea_mm2: 1.28; SizeX_mm: 1.6; SizeY_mm: 0.8; EIA_Code: E96; U/M: EA; AEC Category: Q200; Green_Lifecycle: Active; Green_REACh: Passed
signal-integrity model Resistor
simulation model Resistor
footprint 0603
footprint 0603M
footprint 0603L
footprint 0603_HV
footprint 0603S
pins: 1, 2

## CRCW06034K22FKEA
designator R?  ValueDisplayed: 4.22k  (hidden comment: CRCW06034K22FKEA)
RES, 4.22 k, 1%, 0.1 W, 0603; Manufacturer: Vishay-Dale; CompType: Resistor; Value: 4.22k; Res_ohm: 4220; Value_Code: 4k22; Tolerance_%: 1; Power_W: 0.1; Value2: 0.1W; VDC_V: 75; TempCo: 100 ppm/C; SizeArea_mm2: 1.28; SizeX_mm: 1.6; SizeY_mm: 0.8; EIA_Code: E96; U/M: EA; AEC Category: Q200; Green_Lifecycle: Active; Green_REACh: Passed
signal-integrity model Resistor
simulation model Resistor
footprint 0603
footprint 0603M
footprint 0603L
footprint 0603_HV
footprint 0603S
pins: 1, 2

## CRCW06034K30JNEA
designator R?  ValueDisplayed: 4.3k  (hidden comment: CRCW06034K30JNEA)
RES, 4.3 k, 5%, 0.1 W, 0603; Manufacturer: Vishay-Dale; CompType: Resistor; Value: 4.3k; Res_ohm: 4300; Value_Code: 4k30; Tolerance_%: 5; Power_W: 0.1; Value2: 0.1W; VDC_V: 75; TempCo: 200 ppm/C; SizeArea_mm2: 1.28; SizeX_mm: 1.6; SizeY_mm: 0.8; SizeZ_mm: 1; EIA_Code: E24; U/M: EA; AEC Category: Q200; Green_Lifecycle: Active; Green_REACh: Passed
signal-integrity model Resistor
simulation model Resistor
footprint 0603
footprint 0603M
footprint 0603L
footprint 0603_HV
footprint 0603S
pins: 1, 2

## CRCW06034K32FKEA
designator R?  ValueDisplayed: 4.32k  (hidden comment: CRCW06034K32FKEA)
RES, 4.32 k, 1%, 0.1 W, 0603; Manufacturer: Vishay-Dale; CompType: Resistor; Value: 4.32k; Res_ohm: 4320; Value_Code: 4k32; Tolerance_%: 1; Power_W: 0.1; Value2: 0.1W; VDC_V: 75; TempCo: 100 ppm/C; SizeArea_mm2: 1.28; SizeX_mm: 1.6; SizeY_mm: 0.8; EIA_Code: E96; U/M: EA; AEC Category: Q200; Green_Lifecycle: Active; Green_REACh: Passed
signal-integrity model Resistor
simulation model Resistor
footprint 0603
footprint 0603M
footprint 0603L
footprint 0603_HV
footprint 0603S
pins: 1, 2

## CRCW06034K42FKEA
designator R?  ValueDisplayed: 4.42k  (hidden comment: CRCW06034K42FKEA)
RES, 4.42 k, 1%, 0.1 W, 0603; Manufacturer: Vishay-Dale; CompType: Resistor; Value: 4.42k; Res_ohm: 4420; Value_Code: 4k42; Tolerance_%: 1; Power_W: 0.1; Value2: 0.1W; VDC_V: 75; TempCo: 100 ppm/C; SizeArea_mm2: 1.28; SizeX_mm: 1.6; SizeY_mm: 0.8; EIA_Code: E96; U/M: EA; AEC Category: Q200; Green_Lifecycle: Active; Green_REACh: Passed
signal-integrity model Resistor
simulation model Resistor
footprint 0603
footprint 0603M
footprint 0603L
footprint 0603_HV
footprint 0603S
pins: 1, 2

## CRCW06034K53FKEA
designator R?  ValueDisplayed: 4.53k  (hidden comment: CRCW06034K53FKEA)
RES, 4.53 k, 1%, 0.1 W, 0603; Manufacturer: Vishay-Dale; CompType: Resistor; Value: 4.53k; Res_ohm: 4530; Value_Code: 4k53; Tolerance_%: 1; Power_W: 0.1; Value2: 0.1W; VDC_V: 75; TempCo: 100 ppm/C; SizeArea_mm2: 1.28; SizeX_mm: 1.6; SizeY_mm: 0.8; EIA_Code: E96; U/M: EA; AEC Category: Q200
signal-integrity model Resistor
simulation model Resistor
footprint 0603
footprint 0603M
footprint 0603L
footprint 0603_HV
footprint 0603S
pins: 1, 2

## CRCW06034K64FKEA
designator R?  ValueDisplayed: 4.64k  (hidden comment: CRCW06034K64FKEA)
RES, 4.64 k, 1%, 0.1 W, 0603; Manufacturer: Vishay-Dale; CompType: Resistor; Value: 4.64k; Res_ohm: 4640; Value_Code: 4k64; Tolerance_%: 1; Power_W: 0.1; Value2: 0.1W; VDC_V: 75; TempCo: 100 ppm/C; SizeArea_mm2: 1.28; SizeX_mm: 1.6; SizeY_mm: 0.8; EIA_Code: E96; U/M: EA; AEC Category: Q200; Green_Lifecycle: Active; Green_REACh: Passed
signal-integrity model Resistor
simulation model Resistor
footprint 0603
footprint 0603M
footprint 0603L
footprint 0603_HV
footprint 0603S
pins: 1, 2

## CRCW06034K70JNEA
designator R?  ValueDisplayed: 4.7k  (hidden comment: CRCW06034K70JNEA)
RES, 4.7 k, 5%, 0.1 W, 0603; Manufacturer: Vishay-Dale; CompType: Resistor; Value: 4.7k; Res_ohm: 4700; Value_Code: 4k70; Tolerance_%: 5; Power_W: 0.1; Value2: 0.1W; VDC_V: 75; TempCo: 200 ppm/C; SizeArea_mm2: 1.28; SizeX_mm: 1.6; SizeY_mm: 0.8; SizeZ_mm: 1; EIA_Code: E24; U/M: EA; AEC Category: Q200; Green_Lifecycle: Active; Green_REACh: Passed
signal-integrity model Resistor
simulation model Resistor
footprint 0603
footprint 0603M
footprint 0603L
footprint 0603_HV
footprint 0603S
pins: 1, 2

## CRCW06034K75FKEA
designator R?  ValueDisplayed: 4.75k  (hidden comment: CRCW06034K75FKEA)
RES, 4.75 k, 1%, 0.1 W, 0603; Manufacturer: Vishay-Dale; CompType: Resistor; Value: 4.75k; Res_ohm: 4750; Value_Code: 4k75; Tolerance_%: 1; Power_W: 0.1; Value2: 0.1W; VDC_V: 75; TempCo: 100 ppm/C; SizeArea_mm2: 1.28; SizeX_mm: 1.6; SizeY_mm: 0.8; EIA_Code: E96; U/M: EA; AEC Category: Q200; Green_Lifecycle: Active; Green_REACh: Passed
signal-integrity model Resistor
simulation model Resistor
footprint 0603
footprint 0603M
footprint 0603L
footprint 0603_HV
footprint 0603S
pins: 1, 2

## CRCW06034K87FKEA
designator R?  ValueDisplayed: 4.87k  (hidden comment: CRCW06034K87FKEA)
RES, 4.87 k, 1%, 0.1 W, 0603; Manufacturer: Vishay-Dale; CompType: Resistor; Value: 4.87k; Res_ohm: 4870; Value_Code: 4k87; Tolerance_%: 1; Power_W: 0.1; Value2: 0.1W; VDC_V: 75; TempCo: 100 ppm/C; SizeArea_mm2: 1.28; SizeX_mm: 1.6; SizeY_mm: 0.8; EIA_Code: E96; U/M: EA; AEC Category: Q200; Green_Lifecycle: Active; Green_REACh: Passed
signal-integrity model Resistor
simulation model Resistor
footprint 0603
footprint 0603M
footprint 0603L
footprint 0603_HV
footprint 0603S
pins: 1, 2

## CRCW06034K99FKEA
designator R?  ValueDisplayed: 4.99k  (hidden comment: CRCW06034K99FKEA)
RES, 4.99 k, 1%, 0.1 W, 0603; Manufacturer: Vishay-Dale; CompType: Resistor; Value: 4.99k; Res_ohm: 4990; Value_Code: 4k99; Tolerance_%: 1; Power_W: 0.1; Value2: 0.1W; VDC_V: 75; TempCo: 100 ppm/C; SizeArea_mm2: 1.28; SizeX_mm: 1.6; SizeY_mm: 0.8; EIA_Code: E96; U/M: EA; AEC Category: Q200; Green_Lifecycle: Active; Green_REACh: Passed
signal-integrity model Resistor
simulation model Resistor
footprint 0603
footprint 0603M
footprint 0603L
footprint 0603_HV
footprint 0603S
pins: 1, 2

## CRCW06034M02FKEA
designator R?  ValueDisplayed: 4.02M  (hidden comment: CRCW06034M02FKEA)
RES, 4.02 M, 1%, 0.1 W, 0603; Manufacturer: Vishay-Dale; CompType: Resistor; Value: 4.02Meg; Res_ohm: 4020000; Value_Code: 4M02; Tolerance_%: 1; Power_W: 0.1; Value2: 0.1W; VDC_V: 75; TempCo: 100 ppm/C; SizeArea_mm2: 1.28; SizeX_mm: 1.6; SizeY_mm: 0.8; EIA_Code: E96; U/M: EA; AEC Category: Q200
signal-integrity model Resistor
simulation model Resistor
footprint 0603
footprint 0603M
footprint 0603L
footprint 0603_HV
footprint 0603S
pins: 1, 2

## CRCW06034M12FKEA
designator R?  ValueDisplayed: 4.12M  (hidden comment: CRCW06034M12FKEA)
RES, 4.12 M, 1%, 0.1 W, 0603; Manufacturer: Vishay-Dale; CompType: Resistor; Value: 4.12Meg; Res_ohm: 4120000; Value_Code: 4M12; Tolerance_%: 1; Power_W: 0.1; Value2: 0.1W; VDC_V: 75; TempCo: 100 ppm/C; SizeArea_mm2: 1.28; SizeX_mm: 1.6; SizeY_mm: 0.8; EIA_Code: E96; U/M: EA; AEC Category: Q200
signal-integrity model Resistor
simulation model Resistor
footprint 0603
footprint 0603M
footprint 0603L
footprint 0603_HV
footprint 0603S
pins: 1, 2

## CRCW06034M22FKEA
designator R?  ValueDisplayed: 4.22M  (hidden comment: CRCW06034M22FKEA)
RES, 4.22 M, 1%, 0.1 W, 0603; Manufacturer: Vishay-Dale; CompType: Resistor; Value: 4.22Meg; Res_ohm: 4220000; Value_Code: 4M22; Tolerance_%: 1; Power_W: 0.1; Value2: 0.1W; VDC_V: 75; TempCo: 100 ppm/C; SizeArea_mm2: 1.28; SizeX_mm: 1.6; SizeY_mm: 0.8; EIA_Code: E96; U/M: EA; AEC Category: Q200; Green_Lifecycle: Active; Green_REACh: Passed
signal-integrity model Resistor
simulation model Resistor
footprint 0603
footprint 0603M
footprint 0603L
footprint 0603_HV
footprint 0603S
pins: 1, 2

## CRCW06034M30JNEA
designator R?  ValueDisplayed: 4.3M  (hidden comment: CRCW06034M30JNEA)
RES, 4.3 M, 5%, 0.1 W, 0603; Manufacturer: Vishay-Dale; CompType: Resistor; Value: 4.3Meg; Res_ohm: 4300000; Value_Code: 4M30; Tolerance_%: 5; Power_W: 0.1; Value2: 0.1W; VDC_V: 75; TempCo: 200 ppm/C; SizeArea_mm2: 1.28; SizeX_mm: 1.6; SizeY_mm: 0.8; SizeZ_mm: 1; EIA_Code: E24; U/M: EA; AEC Category: Q200
signal-integrity model Resistor
simulation model Resistor
footprint 0603
footprint 0603M
footprint 0603L
footprint 0603_HV
footprint 0603S
pins: 1, 2

## CRCW06034M32FKEA
designator R?  ValueDisplayed: 4.32M  (hidden comment: CRCW06034M32FKEA)
RES, 4.32 M, 1%, 0.1 W, 0603; Manufacturer: Vishay-Dale; CompType: Resistor; Value: 4.32Meg; Res_ohm: 4320000; Value_Code: 4M32; Tolerance_%: 1; Power_W: 0.1; Value2: 0.1W; VDC_V: 75; TempCo: 100 ppm/C; SizeArea_mm2: 1.28; SizeX_mm: 1.6; SizeY_mm: 0.8; EIA_Code: E96; U/M: EA; AEC Category: Q200; Green_Lifecycle: Active; Green_REACh: Passed
signal-integrity model Resistor
simulation model Resistor
footprint 0603
footprint 0603M
footprint 0603L
footprint 0603_HV
footprint 0603S
pins: 1, 2

## CRCW06034M42FKEA
designator R?  ValueDisplayed: 4.42M  (hidden comment: CRCW06034M42FKEA)
RES, 4.42 M, 1%, 0.1 W, 0603; Manufacturer: Vishay-Dale; CompType: Resistor; Value: 4.42Meg; Res_ohm: 4420000; Value_Code: 4M42; Tolerance_%: 1; Power_W: 0.1; Value2: 0.1W; VDC_V: 75; TempCo: 100 ppm/C; SizeArea_mm2: 1.28; SizeX_mm: 1.6; SizeY_mm: 0.8; EIA_Code: E96; U/M: EA; AEC Category: Q200
signal-integrity model Resistor
simulation model Resistor
footprint 0603
footprint 0603M
footprint 0603L
footprint 0603_HV
footprint 0603S
pins: 1, 2

## CRCW06034M53FKEA
designator R?  ValueDisplayed: 4.53M  (hidden comment: CRCW06034M53FKEA)
RES, 4.53 M, 1%, 0.1 W, 0603; Manufacturer: Vishay-Dale; CompType: Resistor; Value: 4.53Meg; Res_ohm: 4530000; Value_Code: 4M53; Tolerance_%: 1; Power_W: 0.1; Value2: 0.1W; VDC_V: 75; TempCo: 100 ppm/C; SizeArea_mm2: 1.28; SizeX_mm: 1.6; SizeY_mm: 0.8; EIA_Code: E96; U/M: EA; AEC Category: Q200
signal-integrity model Resistor
simulation model Resistor
footprint 0603
footprint 0603M
footprint 0603L
footprint 0603_HV
footprint 0603S
pins: 1, 2

## CRCW06034M64FKEA
designator R?  ValueDisplayed: 4.64M  (hidden comment: CRCW06034M64FKEA)
RES, 4.64 M, 1%, 0.1 W, 0603; Manufacturer: Vishay-Dale; CompType: Resistor; Value: 4.64Meg; Res_ohm: 4640000; Value_Code: 4M64; Tolerance_%: 1; Power_W: 0.1; Value2: 0.1W; VDC_V: 75; TempCo: 100 ppm/C; SizeArea_mm2: 1.28; SizeX_mm: 1.6; SizeY_mm: 0.8; EIA_Code: E96; U/M: EA; AEC Category: Q200
signal-integrity model Resistor
simulation model Resistor
footprint 0603
footprint 0603M
footprint 0603L
footprint 0603_HV
footprint 0603S
pins: 1, 2

## CRCW06034M70JNEA
designator R?  ValueDisplayed: 4.7M  (hidden comment: CRCW06034M70JNEA)
RES, 4.7 M, 5%, 0.1 W, 0603; Manufacturer: Vishay-Dale; CompType: Resistor; Value: 4.7Meg; Res_ohm: 4700000; Value_Code: 4M70; Tolerance_%: 5; Power_W: 0.1; Value2: 0.1W; VDC_V: 75; TempCo: 200 ppm/C; SizeArea_mm2: 1.28; SizeX_mm: 1.6; SizeY_mm: 0.8; SizeZ_mm: 1; EIA_Code: E24; U/M: EA; AEC Category: Q200; Green_Lifecycle: Active; Green_REACh: Passed
signal-integrity model Resistor
simulation model Resistor
footprint 0603
footprint 0603M
footprint 0603L
footprint 0603_HV
footprint 0603S
pins: 1, 2

## CRCW06034M75FKEA
designator R?  ValueDisplayed: 4.75M  (hidden comment: CRCW06034M75FKEA)
RES, 4.75 M, 1%, 0.1 W, 0603; Manufacturer: Vishay-Dale; CompType: Resistor; Value: 4.75Meg; Res_ohm: 4750000; Value_Code: 4M75; Tolerance_%: 1; Power_W: 0.1; Value2: 0.1W; VDC_V: 75; TempCo: 100 ppm/C; SizeArea_mm2: 1.28; SizeX_mm: 1.6; SizeY_mm: 0.8; EIA_Code: E96; U/M: EA; AEC Category: Q200
signal-integrity model Resistor
simulation model Resistor
footprint 0603
footprint 0603M
footprint 0603L
footprint 0603_HV
footprint 0603S
pins: 1, 2

## CRCW06034M87FKEA
designator R?  ValueDisplayed: 4.87M  (hidden comment: CRCW06034M87FKEA)
RES, 4.87 M, 1%, 0.1 W, 0603; Manufacturer: Vishay-Dale; CompType: Resistor; Value: 4.87Meg; Res_ohm: 4870000; Value_Code: 4M87; Tolerance_%: 1; Power_W: 0.1; Value2: 0.1W; VDC_V: 75; TempCo: 100 ppm/C; SizeArea_mm2: 1.28; SizeX_mm: 1.6; SizeY_mm: 0.8; EIA_Code: E96; U/M: EA; AEC Category: Q200
signal-integrity model Resistor
simulation model Resistor
footprint 0603
footprint 0603M
footprint 0603L
footprint 0603_HV
footprint 0603S
pins: 1, 2

## CRCW06034M99FKEA
designator R?  ValueDisplayed: 4.99M  (hidden comment: CRCW06034M99FKEA)
RES, 4.99 M, 1%, 0.1 W, 0603; Manufacturer: Vishay-Dale; CompType: Resistor; Value: 4.99Meg; Res_ohm: 4990000; Value_Code: 4M99; Tolerance_%: 1; Power_W: 0.1; Value2: 0.1W; VDC_V: 75; TempCo: 100 ppm/C; SizeArea_mm2: 1.28; SizeX_mm: 1.6; SizeY_mm: 0.8; EIA_Code: E96; U/M: EA; AEC Category: Q200; Green_Lifecycle: Active; Green_REACh: Passed
signal-integrity model Resistor
simulation model Resistor
footprint 0603
footprint 0603M
footprint 0603L
footprint 0603_HV
footprint 0603S
pins: 1, 2

## CRCW06034R02FKEA
designator R?  ValueDisplayed: 4.02  (hidden comment: CRCW06034R02FKEA)
RES, 4.02, 1%, 0.1 W, 0603; Manufacturer: Vishay-Dale; CompType: Resistor; Value: 4.02; Value_Code: 4R02; Tolerance_%: 1; Power_W: 0.1; Value2: 0.1W; VDC_V: 75; TempCo: 100 ppm/C; SizeArea_mm2: 1.28; SizeX_mm: 1.6; SizeY_mm: 0.8; EIA_Code: E96; U/M: EA; AEC Category: Q200
signal-integrity model Resistor
simulation model Resistor
footprint 0603
footprint 0603M
footprint 0603L
footprint 0603_HV
footprint 0603S
pins: 1, 2

## CRCW06034R12FKEA
designator R?  ValueDisplayed: 4.12  (hidden comment: CRCW06034R12FKEA)
RES, 4.12, 1%, 0.1 W, 0603; Manufacturer: Vishay-Dale; CompType: Resistor; Value: 4.12; Value_Code: 4R12; Tolerance_%: 1; Power_W: 0.1; Value2: 0.1W; VDC_V: 75; TempCo: 100 ppm/C; SizeArea_mm2: 1.28; SizeX_mm: 1.6; SizeY_mm: 0.8; EIA_Code: E96; U/M: EA; AEC Category: Q200
signal-integrity model Resistor
simulation model Resistor
footprint 0603
footprint 0603M
footprint 0603L
footprint 0603_HV
footprint 0603S
pins: 1, 2

## CRCW06034R22FKEA
designator R?  ValueDisplayed: 4.22  (hidden comment: CRCW06034R22FKEA)
RES, 4.22, 1%, 0.1 W, 0603; Manufacturer: Vishay-Dale; CompType: Resistor; Value: 4.22; Value_Code: 4R22; Tolerance_%: 1; Power_W: 0.1; Value2: 0.1W; VDC_V: 75; TempCo: 100 ppm/C; SizeArea_mm2: 1.28; SizeX_mm: 1.6; SizeY_mm: 0.8; EIA_Code: E96; U/M: EA; AEC Category: Q200
signal-integrity model Resistor
simulation model Resistor
footprint 0603
footprint 0603M
footprint 0603L
footprint 0603_HV
footprint 0603S
pins: 1, 2

## CRCW06034R30JNEA
designator R?  ValueDisplayed: 4.3  (hidden comment: CRCW06034R30JNEA)
RES, 4.3, 5%, 0.1 W, 0603; Manufacturer: Vishay-Dale; CompType: Resistor; Value: 4.3; Value_Code: 4R30; Tolerance_%: 5; Power_W: 0.1; Value2: 0.1W; VDC_V: 75; TempCo: 200 ppm/C; SizeArea_mm2: 1.28; SizeX_mm: 1.6; SizeY_mm: 0.8; SizeZ_mm: 1; EIA_Code: E24; U/M: EA; AEC Category: Q200
signal-integrity model Resistor
simulation model Resistor
footprint 0603
footprint 0603M
footprint 0603L
footprint 0603_HV
footprint 0603S
pins: 1, 2

## CRCW06034R32FKEA
designator R?  ValueDisplayed: 4.32  (hidden comment: CRCW06034R32FKEA)
RES, 4.32, 1%, 0.1 W, 0603; Manufacturer: Vishay-Dale; CompType: Resistor; Value: 4.32; Value_Code: 4R32; Tolerance_%: 1; Power_W: 0.1; Value2: 0.1W; VDC_V: 75; TempCo: 100 ppm/C; SizeArea_mm2: 1.28; SizeX_mm: 1.6; SizeY_mm: 0.8; EIA_Code: E96; U/M: EA; AEC Category: Q200
signal-integrity model Resistor
simulation model Resistor
footprint 0603
footprint 0603M
footprint 0603L
footprint 0603_HV
footprint 0603S
pins: 1, 2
